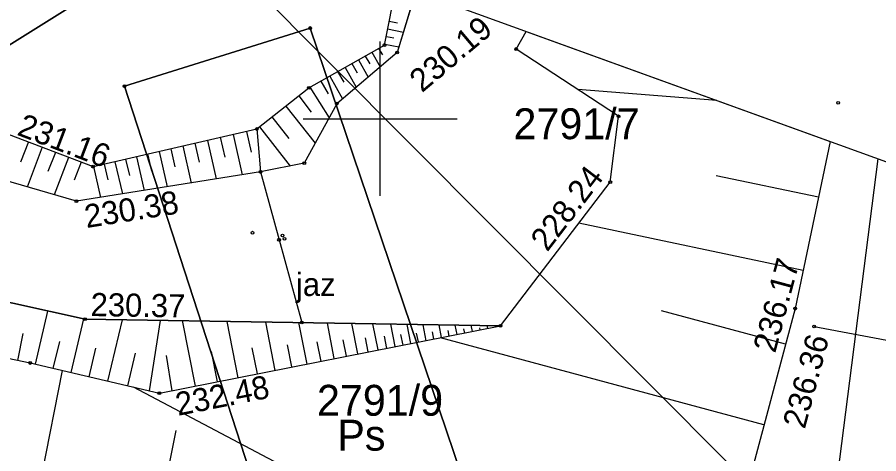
# Model space of a CAD drawing. Extents: x 6596400 to 6597200, y 5539751 to 5540251.
# Drawn here: x 6596788.23 to 6596816.16, y 5540090.15 to 5540104.29 of the extents above; entities that cross this region are included whole.
import ezdxf

# ---------------------------------------------------------------- set-up
doc = ezdxf.new("R2010")
doc.units = 0
for name, color, linetype in [('000 Inne (niezydentyfikowane)', 7, 'Continuous'), ('140-Punkty robocze', 7, 'Continuous'), ('203-punkt graniczny', 7, 'Continuous'), ('210-oznaczenie konturu użytku gruntowego', 7, 'Continuous'), ('211-numer działki ewidencyjnej', 7, 'Continuous'), ('217-kontur klasyfikacyjny', 7, 'Continuous'), ('218-kontur użytku gruntowego', 7, 'Continuous'), ('219-działka ewidencyjna', 7, 'Continuous'), ('brama', 7, 'Continuous'), ('jaz', 7, 'Continuous'), ('jaz-Atr17', 7, 'Continuous'), ('jezdnia', 7, 'Continuous'), ('obudowa ochronna przewodu', 7, 'Continuous'), ('pikieta sztuczna', 7, 'Continuous'), ('pikieta sztuczna-Atr2', 7, 'Continuous'), ('przewód telekomunikacyjny podziemny', 7, 'Continuous'), ('skarpa nieumocniona', 7, 'Continuous'), ('skarpa umocniona', 7, 'Continuous'), ('woda płynąca', 7, 'Continuous'), ('Wstawianie ramki sekcyjnej z opisem', 7, 'Continuous'), ('Zakres', 7, 'Continuous')]:
    doc.layers.add(name, color=color, linetype=linetype)

# ---------------------------------------------------------------- blocks, each defined once
blk = doc.blocks.new('203')
blk.add_circle((0, 0), 0.045)
blk = doc.blocks.new('RAMKA500K')
for p, q in [((0, 98.5), (0, 103.5)), ((400, 98.5), (400, 103.5)), ((0, 101), (2.5, 101)), ((397.5, 101), (400, 101))]:
    blk.add_line(p, q)
blk = doc.blocks.new('PW01')
blk.add_circle((0, 0), 0.045)
blk = doc.blocks.new('PIKIETA')
blk.add_circle((0, 0), 0.045)

msp = doc.modelspace()

# ---------------------------------------------------------------- linework, layer by layer
at = {"layer": '000 Inne (niezydentyfikowane)'}
for p, q in [((6596800.29, 5540104.16), (6596800.56, 5540104.11)), ((6596800.24, 5540103.91), (6596800.75, 5540103.81)), ((6596800.2, 5540103.67), (6596800.44, 5540103.62)), ((6596799.95, 5540103.28), (6596800.07, 5540103.07)), ((6596800.15, 5540103.42), (6596800.6, 5540103.33)), ((6596799.3, 5540102.91), (6596799.61, 5540102.35)), ((6596799.51, 5540103.03), (6596799.66, 5540102.78)), ((6596799.73, 5540103.16), (6596800, 5540102.68)), ((6596798.86, 5540102.66), (6596799.22, 5540102.02)), ((6596799.08, 5540102.79), (6596799.25, 5540102.49)), ((6596798.37, 5540102.38), (6596798.78, 5540101.65)), ((6596798.62, 5540102.53), (6596798.82, 5540102.19)), ((6596798.07, 5540102.22), (6596798.31, 5540101.81)), ((6596797.72, 5540102.02), (6596798.34, 5540101.03)), ((6596810.918, 5540101.59), (6596806.41, 5540101.95)), ((6596797.36, 5540101.74), (6596797.76, 5540101.22)), ((6596796.94, 5540101.41), (6596797.89, 5540100.21)), ((6596796.49, 5540101.06), (6596797.04, 5540100.36)), ((6596796.09, 5540100.74), (6596797.08, 5540099.47)), ((6596794.81, 5540100.4), (6596794.96, 5540099.76)), ((6596795.23, 5540100.49), (6596795.53, 5540099.19)), ((6596795.66, 5540100.59), (6596795.82, 5540099.92)), ((6596788.6, 5540100.25), (6596788.34, 5540099.59)), ((6596793.6, 5540100.12), (6596793.87, 5540098.92)), ((6596793.99, 5540100.21), (6596794.13, 5540099.6)), ((6596794.4, 5540100.3), (6596794.68, 5540099.05)), ((6596789.04, 5540100.08), (6596788.55, 5540098.79)), ((6596789.47, 5540099.91), (6596789.23, 5540099.29)), ((6596792.46, 5540099.86), (6596792.59, 5540099.3)), ((6596792.83, 5540099.94), (6596793.09, 5540098.8)), ((6596793.21, 5540100.03), (6596793.34, 5540099.44)), ((6596789.89, 5540099.75), (6596789.43, 5540098.54)), ((6596790.3, 5540099.6), (6596790.08, 5540099.01)), ((6596791.4, 5540099.61), (6596791.64, 5540098.57)), ((6596791.74, 5540099.69), (6596791.87, 5540099.16)), ((6596792.1, 5540099.77), (6596792.35, 5540098.68)), ((6596790.7, 5540099.45), (6596790.93, 5540098.45)), ((6596791.05, 5540099.53), (6596791.17, 5540099.02)), ((6596814.21, 5540098.46), (6596810.89, 5540099.15)), ((6596813.71, 5540096.09), (6596806.44, 5540097.62)), ((6596813.14, 5540093.7), (6596809.12, 5540094.78)), ((6596812.44, 5540091.09), (6596801.95, 5540093.9)), ((6596788.38, 5540086.16), (6596789.7, 5540092.84)), ((6596810.2, 5540082.7), (6596792, 5540092.31)), ((6596792.28, 5540085.38), (6596793.38, 5540090.9))]:
    msp.add_line(p, q, dxfattribs=at)
for points in [[(6596788.83, 5540093.05), (6596789.23, 5540094.77)], [(6596789.98, 5540092.78), (6596790.39, 5540094.52)], [(6596791.17, 5540092.5), (6596791.64, 5540094.49)], [(6596792.52, 5540092.19), (6596792.88, 5540094.47)], [(6596794.01, 5540092.34), (6596793.59, 5540094.46)], [(6596795.4, 5540092.61), (6596795.04, 5540094.43)], [(6596796.6, 5540092.85), (6596796.29, 5540094.41)], [(6596797.63, 5540093.05), (6596797.36, 5540094.4)], [(6596798.51, 5540093.23), (6596798.29, 5540094.38)], [(6596799.27, 5540093.38), (6596799.08, 5540094.37)], [(6596799.93, 5540093.51), (6596799.76, 5540094.36)], [(6596800.49, 5540093.62), (6596800.34, 5540094.35)], [(6596800.99, 5540093.72), (6596800.87, 5540094.34)], [(6596801.49, 5540093.81), (6596801.39, 5540094.33)], [(6596801.99, 5540093.91), (6596801.91, 5540094.32)], [(6596802.49, 5540094.01), (6596802.43, 5540094.31)], [(6596802.99, 5540094.11), (6596802.95, 5540094.31)], [(6596803.49, 5540094.21), (6596803.47, 5540094.3)], [(6596803.74, 5540094.26), (6596803.74, 5540094.28)], [(6596788.25, 5540093.17), (6596788.43, 5540094.04)], [(6596800.22, 5540093.56), (6596800.14, 5540093.96)], [(6596800.74, 5540093.67), (6596800.67, 5540094.01)], [(6596801.24, 5540093.77), (6596801.18, 5540094.05)], [(6596801.74, 5540093.86), (6596801.69, 5540094.1)], [(6596802.24, 5540093.96), (6596802.2, 5540094.14)], [(6596802.74, 5540094.06), (6596802.71, 5540094.19)], [(6596803.24, 5540094.16), (6596803.23, 5540094.23)], [(6596789.4, 5540092.91), (6596789.61, 5540093.78)], [(6596797.13, 5540092.96), (6596796.99, 5540093.68)], [(6596798.09, 5540093.14), (6596797.96, 5540093.77)], [(6596798.91, 5540093.31), (6596798.8, 5540093.84)], [(6596799.61, 5540093.45), (6596799.52, 5540093.9)], [(6596790.56, 5540092.64), (6596790.78, 5540093.57)], [(6596791.82, 5540092.35), (6596792.07, 5540093.41)], [(6596794.72, 5540092.48), (6596794.53, 5540093.46)], [(6596796.02, 5540092.74), (6596795.85, 5540093.58)], [(6596793.26, 5540092.19), (6596793.07, 5540093.33)]]:
    msp.add_lwpolyline(points, dxfattribs=at)
at = {"layer": '217-kontur klasyfikacyjny'}
for points in [[(6596791.43, 5540105.56), (6596776.03, 5540095.93)], [(6596797.73, 5540103.94), (6596791.71, 5540102.06)], [(6596791.71, 5540102.06), (6596797.73, 5540103.94)], [(6596805.64, 5540080.59), (6596797.73, 5540103.94)], [(6596797.73, 5540103.94), (6596805.64, 5540080.59)], [(6596791.71, 5540102.06), (6596798.41, 5540081.45)], [(6596798.41, 5540081.45), (6596791.71, 5540102.06)]]:
    msp.add_lwpolyline(points, dxfattribs=at)
at = {"layer": '218-kontur użytku gruntowego'}
for points in [[(6596776.03, 5540095.93), (6596791.43, 5540105.56)], [(6596791.43, 5540105.56), (6596776.03, 5540095.93)], [(6596797.73, 5540103.94), (6596791.71, 5540102.06)], [(6596791.71, 5540102.06), (6596797.73, 5540103.94)], [(6596805.64, 5540080.59), (6596797.73, 5540103.94)], [(6596797.73, 5540103.94), (6596805.64, 5540080.59)], [(6596791.71, 5540102.06), (6596798.41, 5540081.45)], [(6596798.41, 5540081.45), (6596791.71, 5540102.06)]]:
    msp.add_lwpolyline(points, dxfattribs=at)
at = {"layer": '219-działka ewidencyjna'}
for points in [[(6596776.03, 5540095.93), (6596791.43, 5540105.56)], [(6596791.71, 5540102.06), (6596797.73, 5540103.94)], [(6596805.64, 5540080.59), (6596797.73, 5540103.94)], [(6596798.41, 5540081.45), (6596791.71, 5540102.06)]]:
    msp.add_lwpolyline(points, dxfattribs=at)
at = {"layer": 'brama'}
msp.add_lwpolyline([(6596814.07, 5540094.27), (6596819.99, 5540093.16)], dxfattribs=at)
at = {"layer": 'jaz'}
msp.add_lwpolyline([(6596796, 5540100.67), (6596796.12, 5540099.28), (6596796.72, 5540097.08), (6596797.46, 5540094.4)], dxfattribs=at)
at = {"layer": 'jezdnia'}
msp.add_lwpolyline([(6596816.136, 5540099.702), (6596814.5, 5540086.93), (6596812.47, 5540082.2), (6596810.01, 5540078.61), (6596805.94, 5540076.86), (6596810.44, 5540074.77), (6596813.26, 5540073.35), (6596813.26, 5540075.57), (6596813.95, 5540078.37), (6596817.04, 5540086.1), (6596818.162, 5540098.968)], dxfattribs=at)
at = {"layer": 'obudowa ochronna przewodu'}
msp.add_lwpolyline([(6596793.213, 5540107.981), (6596811.35, 5540089.78), (6596822.295, 5540078.976)], dxfattribs=at)
at = {"layer": 'przewód telekomunikacyjny podziemny'}
msp.add_lwpolyline([(6596822.295, 5540078.976), (6596811.35, 5540089.78), (6596793.213, 5540107.981)], dxfattribs=at)
at = {"layer": 'skarpa nieumocniona'}
for points in [[(6596785.94, 5540101.26), (6596790.69, 5540099.45), (6596796, 5540100.67), (6596797.69, 5540102), (6596800.14, 5540103.39), (6596800.53, 5540105.35), (6596801.15, 5540105.13), (6596800.55, 5540103.15), (6596798.59, 5540101.49), (6596797.54, 5540099.56), (6596796.12, 5540099.28), (6596790.15, 5540098.33), (6596785.05, 5540099.81)], [(6596785.94, 5540101.26), (6596790.69, 5540099.45), (6596796, 5540100.67), (6596797.69, 5540102), (6596800.14, 5540103.39), (6596800.53, 5540105.35), (6596801.15, 5540105.13), (6596800.55, 5540103.15), (6596798.59, 5540101.49), (6596797.54, 5540099.56), (6596796.12, 5540099.28), (6596790.15, 5540098.33), (6596785.05, 5540099.81)], [(6596783.42, 5540094.18), (6596788.65, 5540093.09), (6596792.84, 5540092.11), (6596803.9, 5540094.29), (6596807.46, 5540098.95), (6596807.73, 5540101.08), (6596804.41, 5540103.26), (6596804.73, 5540103.83), (6596814.59, 5540100.26), (6596813.45, 5540094.85), (6596811.72, 5540088.39), (6596810.84, 5540084.91), (6596810.68, 5540083.15), (6596808.78, 5540081.38), (6596801.25, 5540081.77), (6596792.35, 5540085.37), (6596783.74, 5540087.08)], [(6596783.42, 5540094.18), (6596788.65, 5540093.09), (6596792.84, 5540092.11), (6596803.9, 5540094.29), (6596807.46, 5540098.95), (6596807.73, 5540101.08), (6596804.41, 5540103.26), (6596804.73, 5540103.83), (6596814.59, 5540100.26), (6596813.45, 5540094.85), (6596811.72, 5540088.39), (6596810.84, 5540084.91), (6596810.68, 5540083.15), (6596808.78, 5540081.38), (6596801.25, 5540081.77), (6596792.35, 5540085.37), (6596783.74, 5540087.08)]]:
    msp.add_lwpolyline(points, dxfattribs=at)
at = {"layer": 'skarpa umocniona'}
msp.add_lwpolyline([(6596768.41, 5540103.97), (6596776.33, 5540098.44), (6596782, 5540095.31), (6596783.42, 5540094.18), (6596788.65, 5540093.09), (6596792.84, 5540092.11), (6596803.9, 5540094.29), (6596790.43, 5540094.51), (6596783.39, 5540096.06), (6596775.99, 5540100.07), (6596769.44, 5540104.84)], close=True, dxfattribs=at)
msp.add_lwpolyline([(6596768.41, 5540103.97), (6596776.33, 5540098.44), (6596782, 5540095.31), (6596783.42, 5540094.18), (6596788.65, 5540093.09), (6596792.84, 5540092.11), (6596803.9, 5540094.29), (6596790.43, 5540094.51), (6596783.39, 5540096.06), (6596775.99, 5540100.07), (6596769.44, 5540104.84)], close=True, dxfattribs=at)
at = {"layer": 'woda płynąca'}
for points in [[(6596801.146, 5540105.126), (6596800.55, 5540103.15), (6596798.59, 5540101.49), (6596797.54, 5540099.56), (6596796.12, 5540099.28), (6596790.15, 5540098.33), (6596785.05, 5540099.81), (6596777.76, 5540103.71), (6596772.25, 5540107.73), (6596766.79, 5540112.11), (6596760.34, 5540113.97), (6596748.88, 5540115.79), (6596744.15, 5540115.57), (6596742.04, 5540114.13), (6596740.39, 5540112.04), (6596739.35, 5540110.21), (6596737.64, 5540097.87), (6596736.29, 5540093.37), (6596736.04, 5540089.3), (6596736.53, 5540085.88)], [(6596783.39, 5540096.06), (6596790.43, 5540094.51), (6596803.9, 5540094.29), (6596807.46, 5540098.95), (6596807.73, 5540101.08), (6596804.41, 5540103.26), (6596804.727, 5540103.83)]]:
    msp.add_lwpolyline(points, dxfattribs=at)
at = {"layer": 'Zakres'}
msp.add_lwpolyline([(6596822.22, 5540097.5), (6596800.39, 5540105.4), (6596755.76, 5540121.45), (6596697.73, 5540120.74), (6596659.35, 5540133.92), (6596647.64, 5540109.28), (6596697.73, 5540077), (6596721.01, 5540057.77), (6596727.72, 5540045.95), (6596731.95, 5540033.61), (6596741.17, 5540031.18), (6596755.59, 5540029.2), (6596757.85, 5540044.22), (6596787.25, 5540055.04), (6596806.3, 5540048.33), (6596813.97, 5540042.6), (6596833.15, 5540068.58), (6596822.3, 5540077.75)], close=True, dxfattribs=at)

# ---------------------------------------------------------------- block references
at = {"layer": '140-Punkty robocze'}
for p in [(6596800.14, 5540103.39), (6596800.55, 5540103.15), (6596804.41, 5540103.26), (6596797.69, 5540102), (6596798.59, 5540101.49), (6596814.85, 5540101.52), (6596807.73, 5540101.08), (6596796, 5540100.67), (6596797.54, 5540099.56), (6596790.69, 5540099.45), (6596796.12, 5540099.28), (6596790.15, 5540098.33), (6596795.86, 5540097.31), (6596796.72, 5540097.08), (6596796.83, 5540097.22), (6596796.9, 5540097.11), (6596790.43, 5540094.51), (6596797.46, 5540094.4), (6596803.9, 5540094.29), (6596788.65, 5540093.09), (6596792.84, 5540092.11)]:
    msp.add_blockref('PIKIETA', p, dxfattribs=at)
at = {"layer": '203-punkt graniczny'}
for p in [(6596797.73, 5540103.94), (6596791.71, 5540102.06)]:
    msp.add_blockref('203', p, dxfattribs=at)
at = {"layer": 'pikieta sztuczna'}
for p in [(6596790.69, 5540099.45), (6596807.46, 5540098.95), (6596790.15, 5540098.33), (6596813.45, 5540094.85), (6596790.43, 5540094.51), (6596814.07, 5540094.27), (6596792.84, 5540092.11)]:
    msp.add_blockref('PW01', p, dxfattribs=at)
at = {"layer": 'Wstawianie ramki sekcyjnej z opisem'}
for p in [(6596400, 5540000), (6596800, 5540000)]:
    msp.add_blockref('RAMKA500K', p, dxfattribs=at)

# ---------------------------------------------------------------- texts
at = {"layer": '210-oznaczenie konturu użytku gruntowego'}
msp.add_text('Ps', height=1, dxfattribs=at).set_placement((6596798.61, 5540090.25))
at = {"layer": '211-numer działki ewidencyjnej'}
for s, p in [('2791/7', (6596804.32, 5540100.34)), ('2791/9', (6596797.95, 5540091.38))]:
    msp.add_text(s, height=1, dxfattribs=at).set_placement(p)
at = {"layer": 'jaz-Atr17'}
msp.add_text('jaz', height=0.75, dxfattribs=at).set_placement((6596797.27, 5540095.26))
at = {"layer": 'pikieta sztuczna-Atr2'}
for s, rotation, p in [('230.19', 40.182, (6596801.354, 5540101.827)), ('231.16', 339.141, (6596788.193, 5540100.489)), ('228.24', 52.622, (6596805.416, 5540096.665)), ('230.38', 9.042, (6596790.478, 5540097.459)), ('236.17', 75.008, (6596812.804, 5540093.386)), ('230.37', 359.064, (6596790.608, 5540094.61)), ('236.36', 75.008, (6596813.764, 5540090.926)), ('232.48', 11.15, (6596793.445, 5540091.374))]:
    msp.add_text(s, height=0.75, rotation=rotation, dxfattribs=at).set_placement(p)

doc.saveas('drawing.dxf')
